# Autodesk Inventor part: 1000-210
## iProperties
Created: 2007-03
Part Number: 1000-210
Document SubType Name: Modeling
Designer: Andy Moles
Material: ABS Plastic
Mass: 27.651 g
Surface Area: 118.694 cm^2
Volume: 26.0858 cm^3
Density: 1.06 g/cm^3
Author: Andy Moles
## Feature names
1. Base1
2. Hole3
